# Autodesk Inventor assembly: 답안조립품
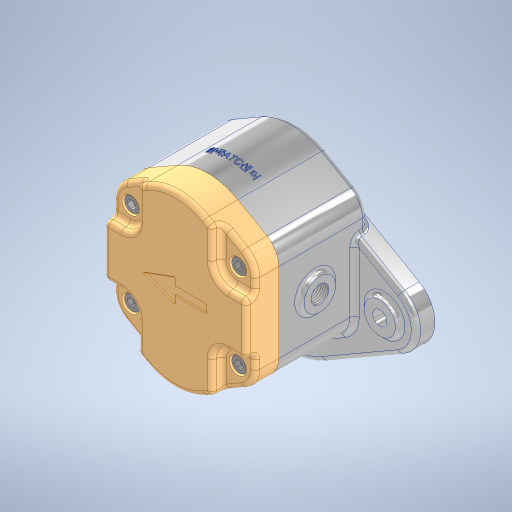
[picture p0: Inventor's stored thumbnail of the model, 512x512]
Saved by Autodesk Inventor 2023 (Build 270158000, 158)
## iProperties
Created: 2025-11
Part Number: 답안조립품
Document SubType Name: Assembly
Designer: home
Author: home
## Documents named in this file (11)
- C:\Users\home\Desktop\751103V1012\답안조립품.iam
- C:\Users\home\Desktop\751103V1012\본체1.ipt
- C:\Users\home\Desktop\751103V1012\커버.ipt
- C:\Users\home\Desktop\751103V1012\3자 실링.ipt
- C:\Users\home\Desktop\751103V1012\6각 구멍붙이 볼트 M6x16.ipt
- C:\Users\home\Desktop\751103V1012\DU 부시.ipt
- C:\Users\home\Desktop\751103V1012\가이드 블록.ipt
- C:\Users\home\Desktop\751103V1012\구동기어.ipt
- C:\Users\home\Desktop\751103V1012\스퍼기어.ipt
- C:\Users\home\Desktop\751103V1012\실링.ipt
- C:\Users\home\Desktop\751103V1012\오일 실 16 30 7.ipt
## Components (11 placed, 5 different names)
1. 3자 실링:1
2. 6각 구멍붙이 볼트 M6x16:1
3. DU 부시:1
4. 가이드 블록:1
5. 구동기어:1
6. DU 부시:2
7. DU 부시:3
8. DU 부시:4
9. 6각 구멍붙이 볼트 M6x16:2
10. 6각 구멍붙이 볼트 M6x16:3
11. 6각 구멍붙이 볼트 M6x16:4
